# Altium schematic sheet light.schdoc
size A3
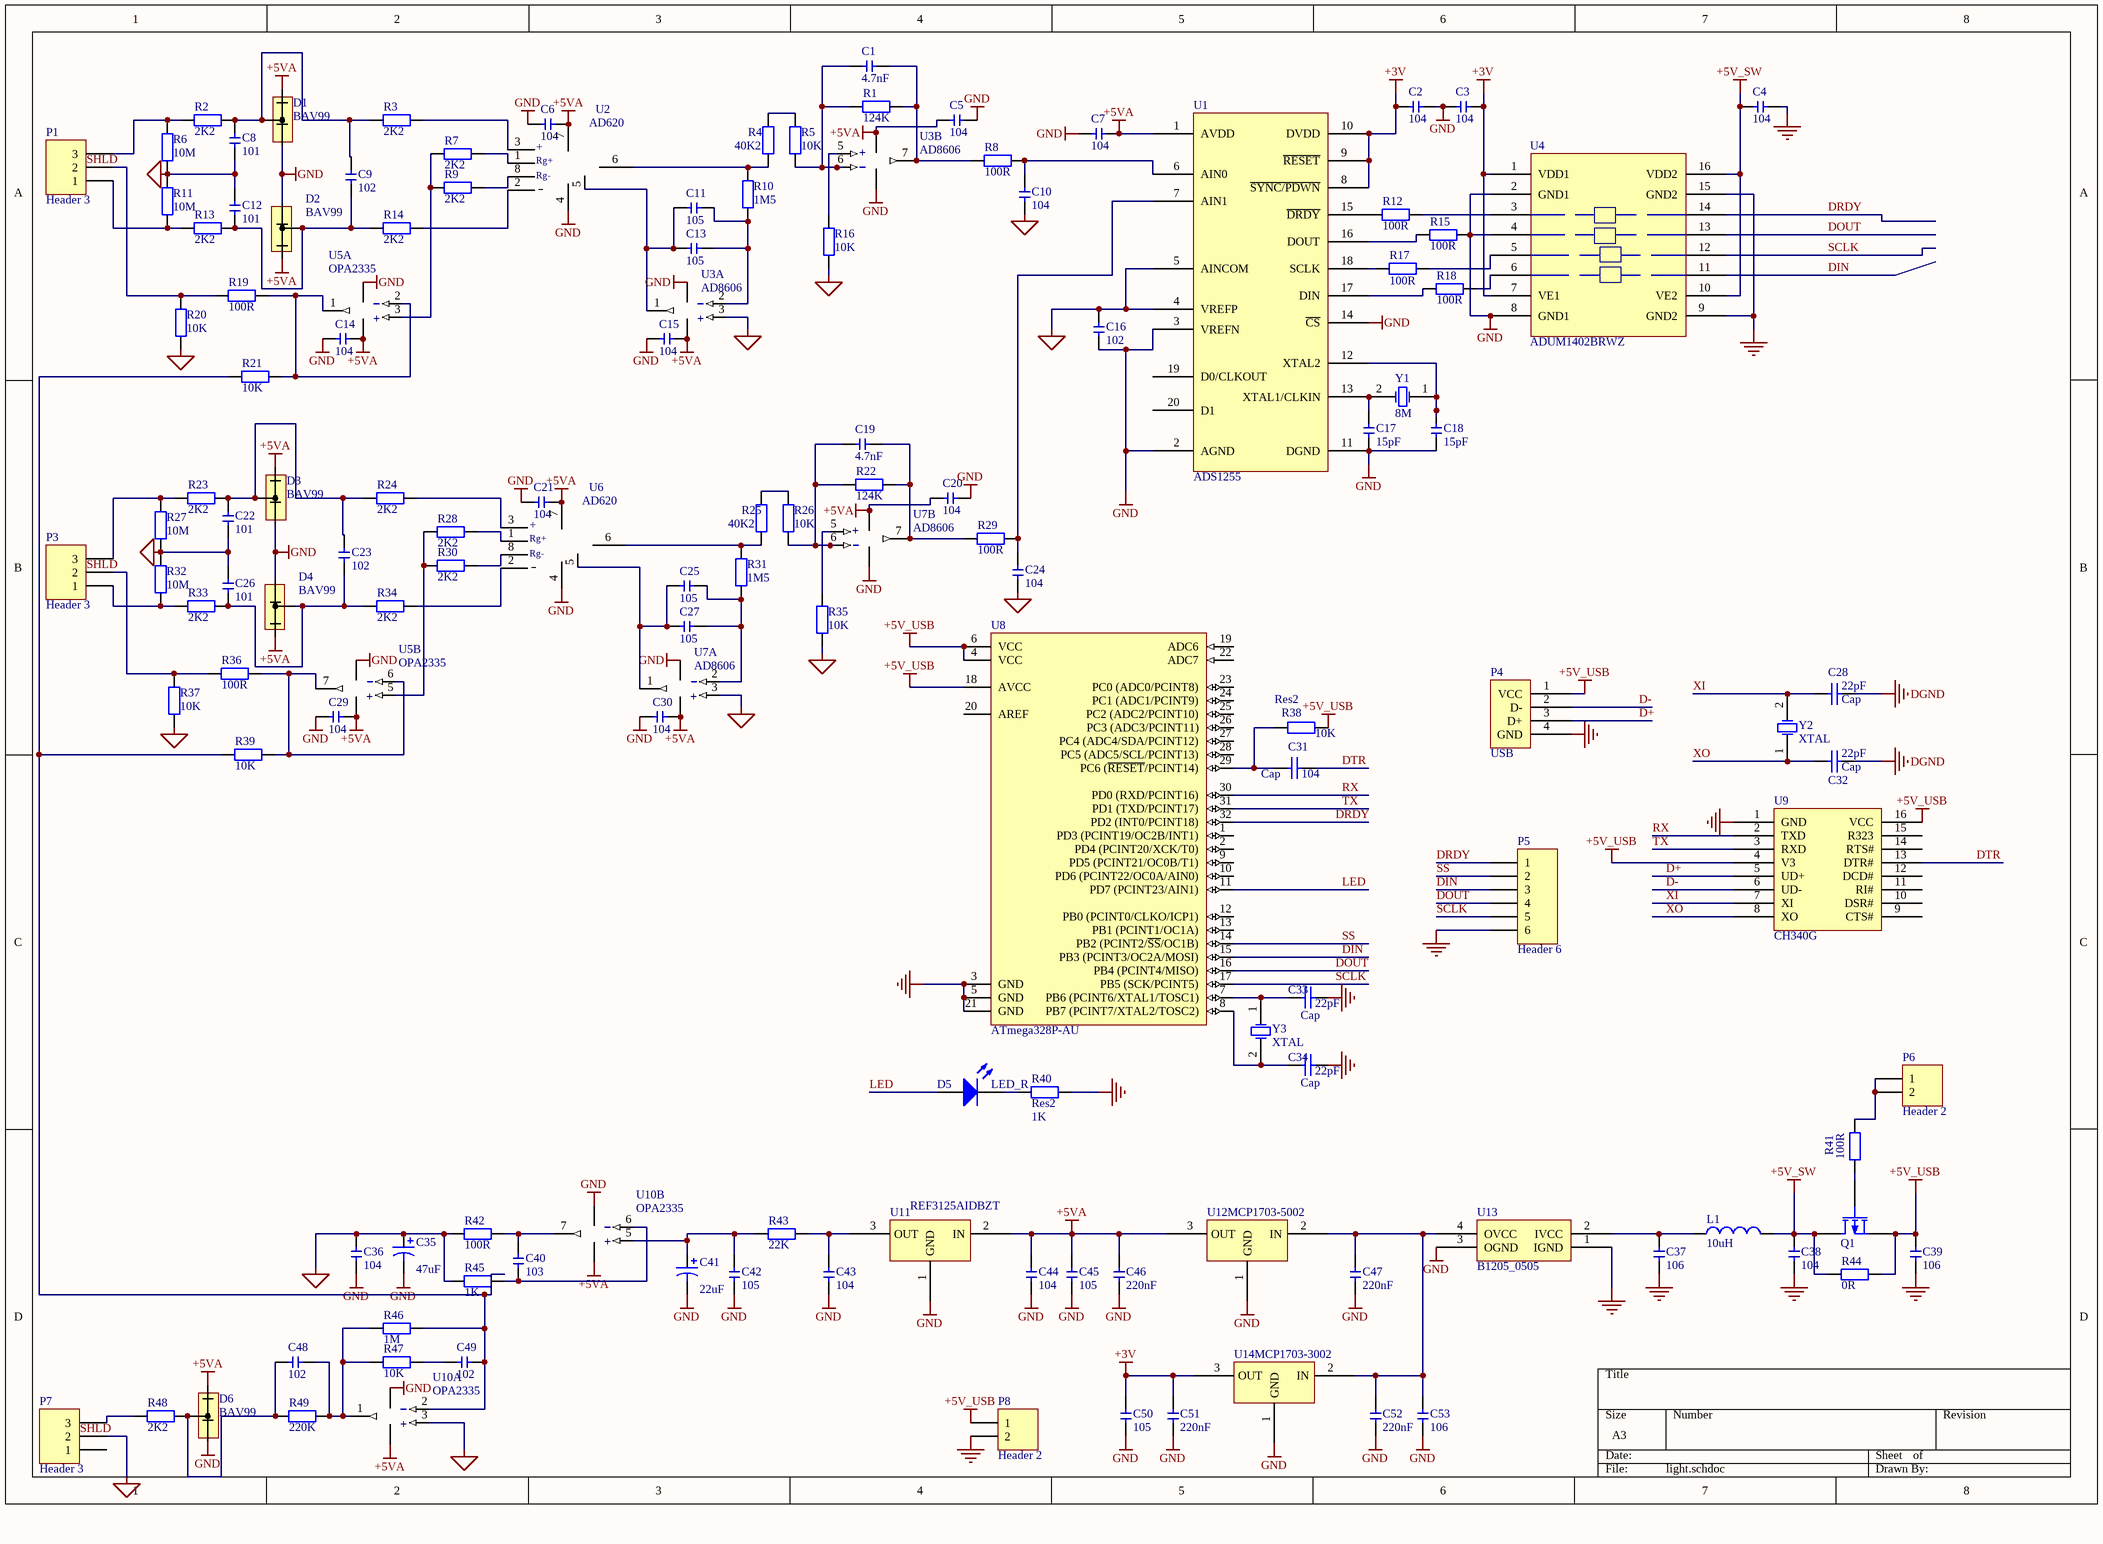
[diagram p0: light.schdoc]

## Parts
C1  value 4.7nF  [0603]  (hidden comment: Cap)
C2  value 104  [0603]  (hidden comment: Cap)
C3  value 104  [0603]  (hidden comment: Cap)
C4  value 104  [0603]  (hidden comment: Cap)
C5  value 104  [0603]  (hidden comment: Cap)
C6  value 104  [0603]  (hidden comment: Cap)
C7  value 104  [0603]  (hidden comment: Cap)
C8  value 101  [0603]  (hidden comment: Cap)
C9  value 102  [0603]  (hidden comment: Cap)
C10  value 104  [0603]  (hidden comment: Cap)
C11  value 105  [0603]  (hidden comment: Cap)
C12  value 101  [0603]  (hidden comment: Cap)
C13  value 105  [0603]  (hidden comment: Cap)
C14  value 104  [0603]  (hidden comment: Cap)
C15  value 104  [0603]  (hidden comment: Cap)
C16  value 102  [0603]  (hidden comment: Cap)
C17  value 15pF  [0603]  (hidden comment: Cap)
C18  value 15pF  [0603]  (hidden comment: Cap)
C19  value 4.7nF  [0603]  (hidden comment: Cap)
C20  value 104  [0603]  (hidden comment: Cap)
C21  value 104  [0603]  (hidden comment: Cap)
C22  value 101  [0603]  (hidden comment: Cap)
C23  value 102  [0603]  (hidden comment: Cap)
C24  value 104  [0603]  (hidden comment: Cap)
C25  value 105  [0603]  (hidden comment: Cap)
C26  value 101  [0603]  (hidden comment: Cap)
C27  value 105  [0603]  (hidden comment: Cap)
C28  Cap  value 22pF  [0603]
C29  value 104  [0603]  (hidden comment: Cap)
C30  value 104  [0603]  (hidden comment: Cap)
C31  Cap  value 104  [0805]
C32  Cap  value 22pF  [0603]
C33  Cap  value 22pF  [0805]
C34  Cap  value 22pF  [0805]
C35  value 47uF  [47uf]  (hidden comment: Cap Pol2)
C36  value 104  [0603]  (hidden comment: Cap)
C37  value 106  [0603]  (hidden comment: Cap)
C38  value 104  [0603]  (hidden comment: Cap)
C39  value 106  [0603]  (hidden comment: Cap)
C40  value 103  [0603]  (hidden comment: Cap)
C41  value 22uF  [47uf]  (hidden comment: Cap Pol2)
C42  value 105  [0603]  (hidden comment: Cap)
C43  value 104  [0603]  (hidden comment: Cap)
C44  value 104  [0603]  (hidden comment: Cap)
C45  value 105  [0603]  (hidden comment: Cap)
C46  value 220nF  [0603]  (hidden comment: Cap)
C47  value 220nF  [0603]  (hidden comment: Cap)
C48  value 102  [0603]  (hidden comment: Cap)
C49  value 102  [0603]  (hidden comment: Cap)
C50  value 105  [0603]  (hidden comment: Cap)
C51  value 220nF  [0603]  (hidden comment: Cap)
C52  value 220nF  [0603]  (hidden comment: Cap)
C53  value 106  [0603]  (hidden comment: Cap)
D1  BAV99
D2  BAV99
D3  BAV99
D4  BAV99
D5  LED_R  [0805_极性]
D6  BAV99
L1  value 10uH  [1206]  (hidden comment: Inductor)
P1  Header 3  [AV]
P3  Header 3  [AV]
P4  USB  [USB_B_DIP]
P5  Header 6  [HDR1X6]
P6  Header 2  [HDR1X2]
P7  Header 3  [AV]
P8  Header 2  [HDR1X2]
Q1  MOSFET-P  [E3]  (value not drawn)
R1  value 124K  [0805]  (hidden comment: Res2)
R2  value 2K2  [0805]  (hidden comment: Res2)
R3  value 2K2  [0805]  (hidden comment: Res2)
R4  value 40K2  [0805]  (hidden comment: Res2)
R5  value 10K  [0805]  (hidden comment: Res2)
R6  value 10M  [0805]  (hidden comment: Res2)
R7  value 2K2  [0805]  (hidden comment: Res2)
R8  value 100R  [0805]  (hidden comment: Res2)
R9  value 2K2  [0805]  (hidden comment: Res2)
R10  value 1M5  [0805]  (hidden comment: Res2)
R11  value 10M  [0805]  (hidden comment: Res2)
R12  value 100R  [0805]  (hidden comment: Res2)
R13  value 2K2  [0805]  (hidden comment: Res2)
R14  value 2K2  [0805]  (hidden comment: Res2)
R15  value 100R  [0805]  (hidden comment: Res2)
R16  value 10K  [0805]  (hidden comment: Res2)
R17  value 100R  [0805]  (hidden comment: Res2)
R18  value 100R  [0805]  (hidden comment: Res2)
R19  value 100R  [0805]  (hidden comment: Res2)
R20  value 10K  [0805]  (hidden comment: Res2)
R21  value 10K  [0805]  (hidden comment: Res2)
R22  value 124K  [0805]  (hidden comment: Res2)
R23  value 2K2  [0805]  (hidden comment: Res2)
R24  value 2K2  [0805]  (hidden comment: Res2)
R25  value 40K2  [0805]  (hidden comment: Res2)
R26  value 10K  [0805]  (hidden comment: Res2)
R27  value 10M  [0805]  (hidden comment: Res2)
R28  value 2K2  [0805]  (hidden comment: Res2)
R29  value 100R  [0805]  (hidden comment: Res2)
R30  value 2K2  [0805]  (hidden comment: Res2)
R31  value 1M5  [0805]  (hidden comment: Res2)
R32  value 10M  [0805]  (hidden comment: Res2)
R33  value 2K2  [0805]  (hidden comment: Res2)
R34  value 2K2  [0805]  (hidden comment: Res2)
R35  value 10K  [0805]  (hidden comment: Res2)
R36  value 100R  [0805]  (hidden comment: Res2)
R37  value 10K  [0805]  (hidden comment: Res2)
R38  Res2  value 10K  [0805]
R39  value 10K  [0805]  (hidden comment: Res2)
R40  Res2  value 1K  [0805]
R41  value 100R  [0805]  (hidden comment: Res2)
R42  value 100R  [0805]  (hidden comment: Res2)
R43  value 22K  [0805]  (hidden comment: Res2)
R44  value 0R  [0805]  (hidden comment: Res2)
R45  value 1K  [0805]  (hidden comment: Res2)
R46  value 1M  [0805]  (hidden comment: Res2)
R47  value 10K  [0805]  (hidden comment: Res2)
R48  value 2K2  [0805]  (hidden comment: Res2)
R49  value 220K  [0805]  (hidden comment: Res2)
U1  ADS1255  [ADS1255]
U2  AD620  [AD620]
U3  AD8606  [AD8606]  (parts A,B of 2)
U4  ADUM1402BRWZ  [ADUM1402BRWZ]
U5  OPA2335  [OPA2335]  (parts A,B of 2)
U6  AD620  [AD620]
U7  AD8606  [AD8606]  (parts A,B of 2)
U8  ATmega328P-AU  [TQFP_32_短PIN]
U9  CH340G  [SOP_16]
U10  OPA2335  [OPA2335]  (parts A,B of 2)
U11  REF3125AIDBZT  [REF3125]
U12  MCP1703-5002  [SOT23]
U13  B1205_0505  [B0505LS]
U14  MCP1703-3002  [SOT23]
Y1  8M  [XTAL_5023]
Y2  XTAL  [XTAL_5032_2PIN]
Y3  XTAL  [XTAL_5032_2PIN]

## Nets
+3V: C2.1 C3.2 C50.1 C51.1 U1.8(~{SYNC/PDWN}) U1.9(~{RESET}) U1.10(DVDD) U4.1(VDD1) U4.7(VE1) U14.3(OUT)
+5V_SW: C4.1 C38.1 L1.2 Q1.1(D) R44.2 U4.10(VE2) U4.16(VDD2)
+5V_USB: C39.1 P4.1(VCC) P8.1 Q1.3(S) R38.2 R44.1 U8.4(VCC) U8.6(VCC) U8.18(AVCC) U9.4(V3) U9.16(VCC)
+5VA: C5.2 C6.2 C7.2 C14.2 C15.2 C20.2 C21.2 C29.2 C30.2 C44.1 C45.1 C46.1 D1.1 D2.1 D3.1 D4.1 D6.1 U1.1(AVDD) U2.7 U3.8 U5.8 U6.7 U7.8 U10.8 U11.2(IN) U12.3(OUT)
AGND: C8.1 C10.2 C12.2 C16.1 C22.1 C24.2 C26.2 C35.1 C36.1 P7.2 R6.1 R11.2 R16.2 R20.2 R27.1 R32.2 R35.2 R37.2 R42.2 R45.2 U1.4(VREFP) U1.5(AINCOM) U3.3 U7.3 U10.3
DGND: C4.2 C28.2 C32.2 C33.1 C34.1 C37.2 C38.2 C39.2 P4.4(GND) P5.6 P8.2 R40.2 U4.9(GND2) U4.15(GND2) U8.3(GND) U8.5(GND) U8.21(GND) U9.1(GND) U13.1(IGND)
GND: C2.2 C3.1 C5.1 C6.1 C7.1 C14.1 C15.1 C16.2 C17.2 C18.2 C20.1 C21.1 C29.1 C30.1 C35.2 C36.2 C41.2 C42.2 C43.2 C44.2 C45.2 C46.2 C47.2 C50.2 C51.2 C52.2 C53.2 D1.3 D2.3 D3.3 D4.3 D6.3 R15.1 U1.2(AGND) U1.3(VREFN) U1.11(DGND) U1.14(~{CS}) U2.4 U3.4 U4.2(GND1) U4.4 U4.8(GND1) U5.4 U6.4 U7.4 U10.4 U11.1(GND) U12.1(GND) U13.3(OGND) U14.1(GND)
D+: P4.3(D+) U9.5(UD+)
D-: P4.2(D-) U9.6(UD-)
DIN: P5.3 U4.11 U8.15(PB3_(PCINT3/OC2A/MOSI))
DOUT: P5.4 U4.13 U8.16(PB4_(PCINT4/MISO))
DRDY: P5.1 U4.14 U8.32(PD2_(INT0/PCINT18))
DTR: C31.1 U9.13(DTR#)
LED: D5.1(A) U8.11(PD7_(PCINT23/AIN1))
RX: U8.30(PD0_(RXD/PCINT16)) U9.2(TXD)
SCLK: P5.5 U4.12 U8.17(PB5_(SCK/PCINT5))
SS: P5.2 U8.14(PB2_(PCINT2/~{SS}/OC1B))
TX: U8.31(PD1_(TXD/PCINT17)) U9.3(RXD)
XI: C28.1 U9.7(XI) Y2.2(OSC2)
XO: C32.1 U9.8(XO) Y2.1(OSC1)
NetC1_1: C1.1 R1.1 R8.2 U3.7
NetC1_2: C1.2 R1.2 R5.1 U3.6
NetC8_2: C8.2 C9.2 D1.2 R2.1 R3.2
NetC9_1: C9.1 C12.1 D2.2 R13.1 R14.2
NetC10_1: C10.1 R8.1 U1.6(AIN0)
NetC11_1: C11.1 C13.1 R10.2 U3.2
NetC11_2: C11.2 C13.2 U2.5 U3.1
NetC17_1: C17.1 U1.13(XTAL1/CLKIN) Y1.2(OSC2)
NetC18_1: C18.1 U1.12(XTAL2) Y1.1(OSC1)
NetC19_1: C19.1 R22.1 R29.2 U7.7
NetC19_2: C19.2 R22.2 R26.1 U7.6
NetC22_2: C22.2 C23.2 D3.2 R23.1 R24.2
NetC23_1: C23.1 C26.1 D4.2 R33.1 R34.2
NetC24_1: C24.1 R29.1 U1.7(AIN1)
NetC25_1: C25.1 C27.1 R31.2 U7.2
NetC25_2: C25.2 C27.2 U6.5 U7.1
NetC31_2: C31.2 R38.1 U8.29(PC6_(~{RESET}/PCINT14))
NetC33_2: C33.2 U8.7(PB6_(PCINT6/XTAL1/TOSC1)) Y3.1(OSC1)
NetC34_2: C34.2 U8.8(PB7_(PCINT7/XTAL2/TOSC2)) Y3.2(OSC2)
NetC37_1: C37.1 L1.1 U13.2(IVCC)
NetC40_1: C40.1 R42.1 U10.7
NetC40_2: C40.2 R45.1 U10.6
NetC41_1: C41.1 C42.1 R43.2 U10.5
NetC43_1: C43.1 R43.1 U11.3(OUT)
NetC47_1: C47.1 C52.1 C53.1 U12.2(IN) U13.4(OVCC) U14.2(IN)
NetC48_1: C48.1 R46.2 R47.2 R49.1 U10.1
NetC48_2: C48.2 D6.2 R48.1 R49.2
NetC49_1: C49.1 R21.2 R39.2 R46.1 U10.2
NetC49_2: C49.2 R47.1
NetD5_2: D5.2(K) R40.1
NetP1_1: P1.1 R11.1 R13.2
NetP1_2: P1.2 R19.2 R20.1
NetP1_3: P1.3 R2.2 R6.2
NetP3_1: P3.1 R32.1 R33.2
NetP3_2: P3.2 R36.2 R37.1
NetP3_3: P3.3 R23.2 R27.2
NetP6_1: P6.1 P6.2 R41.1
NetP7_3: P7.3 R48.2
NetQ1_2: Q1.2(G) R41.2
NetR3_1: R3.1 U2.3
NetR4_1: R4.1 R5.2
NetR4_2: R4.2 R10.1 U2.6
NetR7_1: R7.1 U2.1
NetR7_2: R7.2 R9.2 U5.3
NetR9_1: R9.1 U2.8
NetR12_1: R12.1 U4.3
NetR12_2: R12.2 U1.15(~{DRDY})
NetR14_1: R14.1 U2.2
NetR15_2: R15.2 U1.16(DOUT)
NetR16_1: R16.1 U3.5
NetR17_1: R17.1 U4.5
NetR17_2: R17.2 U1.18(SCLK)
NetR18_1: R18.1 U4.6
NetR18_2: R18.2 U1.17(DIN)
NetR19_1: R19.1 R21.1 U5.1 U5.2
NetR24_1: R24.1 U6.3
NetR25_1: R25.1 R26.2
NetR25_2: R25.2 R31.1 U6.6
NetR28_1: R28.1 U6.1
NetR28_2: R28.2 R30.2 U5.5
NetR30_1: R30.1 U6.8
NetR34_1: R34.1 U6.2
NetR35_1: R35.1 U7.5
NetR36_1: R36.1 R39.1 U5.6 U5.7

Not connected (* = marked no-connect by the designer): P7 1; U1 19(D0/CLKOUT) 20(D1); U8 1(PD3_(PCINT19/OC2B/INT1)) 2(PD4_(PCINT20/XCK/T0)) 9(PD5_(PCINT21/OC0B/T1)) 10(PD6_(PCINT22/OC0A/AIN0)) 12(PB0_(PCINT0/CLKO/ICP1)) 13(PB1_(PCINT1/OC1A)) 19(ADC6) 20(AREF) 22(ADC7) 23(PC0_(ADC0/PCINT8)) 24(PC1_(ADC1/PCINT9)) 25(PC2_(ADC2/PCINT10)) 26(PC3_(ADC3/PCINT11)) 27(PC4_(ADC4/SDA/PCINT12)) 28(PC5_(ADC5/SCL/PCINT13)); U9 9(CTS#) 10(DSR#) 11(RI#) 12(DCD#) 14(RTS#) 15(R323)

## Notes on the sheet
- Labels drawn without touching a wire or pin: SHLD

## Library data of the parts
C1-C34 C36-C40 C42-C53 = Cap: Capacitor
C35 C41 = Cap Pol2: Polarized Capacitor (Axial)
D5 = LED
L1 = Inductor: Code_IEC: 1005
P1 P3 P7 = Header 3: Header, 3-Pin
P5 = Header 6: Header, 6-Pin
P6 P8 = Header 2: Header, 2-Pin
Q1 = MOSFET-P: P-Channel MOSFET
R38 R40 = Res2: Resistor
U8 = ATmega328P-AU: 8-bit AVR Microcontroller, 32KB Flash, 1KB EEPROM, 2KB SRAM, 32-pin TQFP, Industrial Grade (-40°C to 85°C)
U13 = B1205/B0505
Y1 Y3 = XTAL: Crystal Oscillator
Y2 = XTAL: Crystal Oscillator; Value: 12MHz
